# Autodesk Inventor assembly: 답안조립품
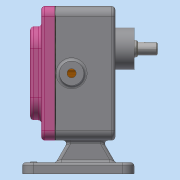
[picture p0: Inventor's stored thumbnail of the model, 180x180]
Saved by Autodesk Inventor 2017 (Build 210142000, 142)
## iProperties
Part Number: 답안조립품
Material: 일반
Document SubType Name: Assembly
Designer: MRC
Author: MRC
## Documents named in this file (11)
- C:\Users\MRC\Desktop\700407V1049\답안조립품.iam
- C:\Users\MRC\Desktop\700407V1049\본체.ipt
- C:\Users\MRC\Desktop\700407V1049\Ű 6 x 6 x 18.ipt
- C:\Users\MRC\Desktop\700407V1049\개스킷.ipt
- C:\Users\MRC\Desktop\700407V1049\메인축.ipt
- C:\Users\MRC\Desktop\700407V1049\베어링부시.ipt
- C:\Users\MRC\Desktop\700407V1049\볼트 M5.ipt
- C:\Users\MRC\Desktop\700407V1049\서브축.ipt
- C:\Users\MRC\Desktop\700407V1049\스퍼기어.ipt
- C:\Users\MRC\Desktop\700407V1049\오일 실 16 28 7.ipt
- C:\Users\MRC\Desktop\700407V1049\커버.ipt
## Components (3 placed, 2 different names)
1. Ű 6 x 6 x 18:1
2. 개스킷:1
3. Ű 6 x 6 x 18:2
